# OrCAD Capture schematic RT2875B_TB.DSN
size A3
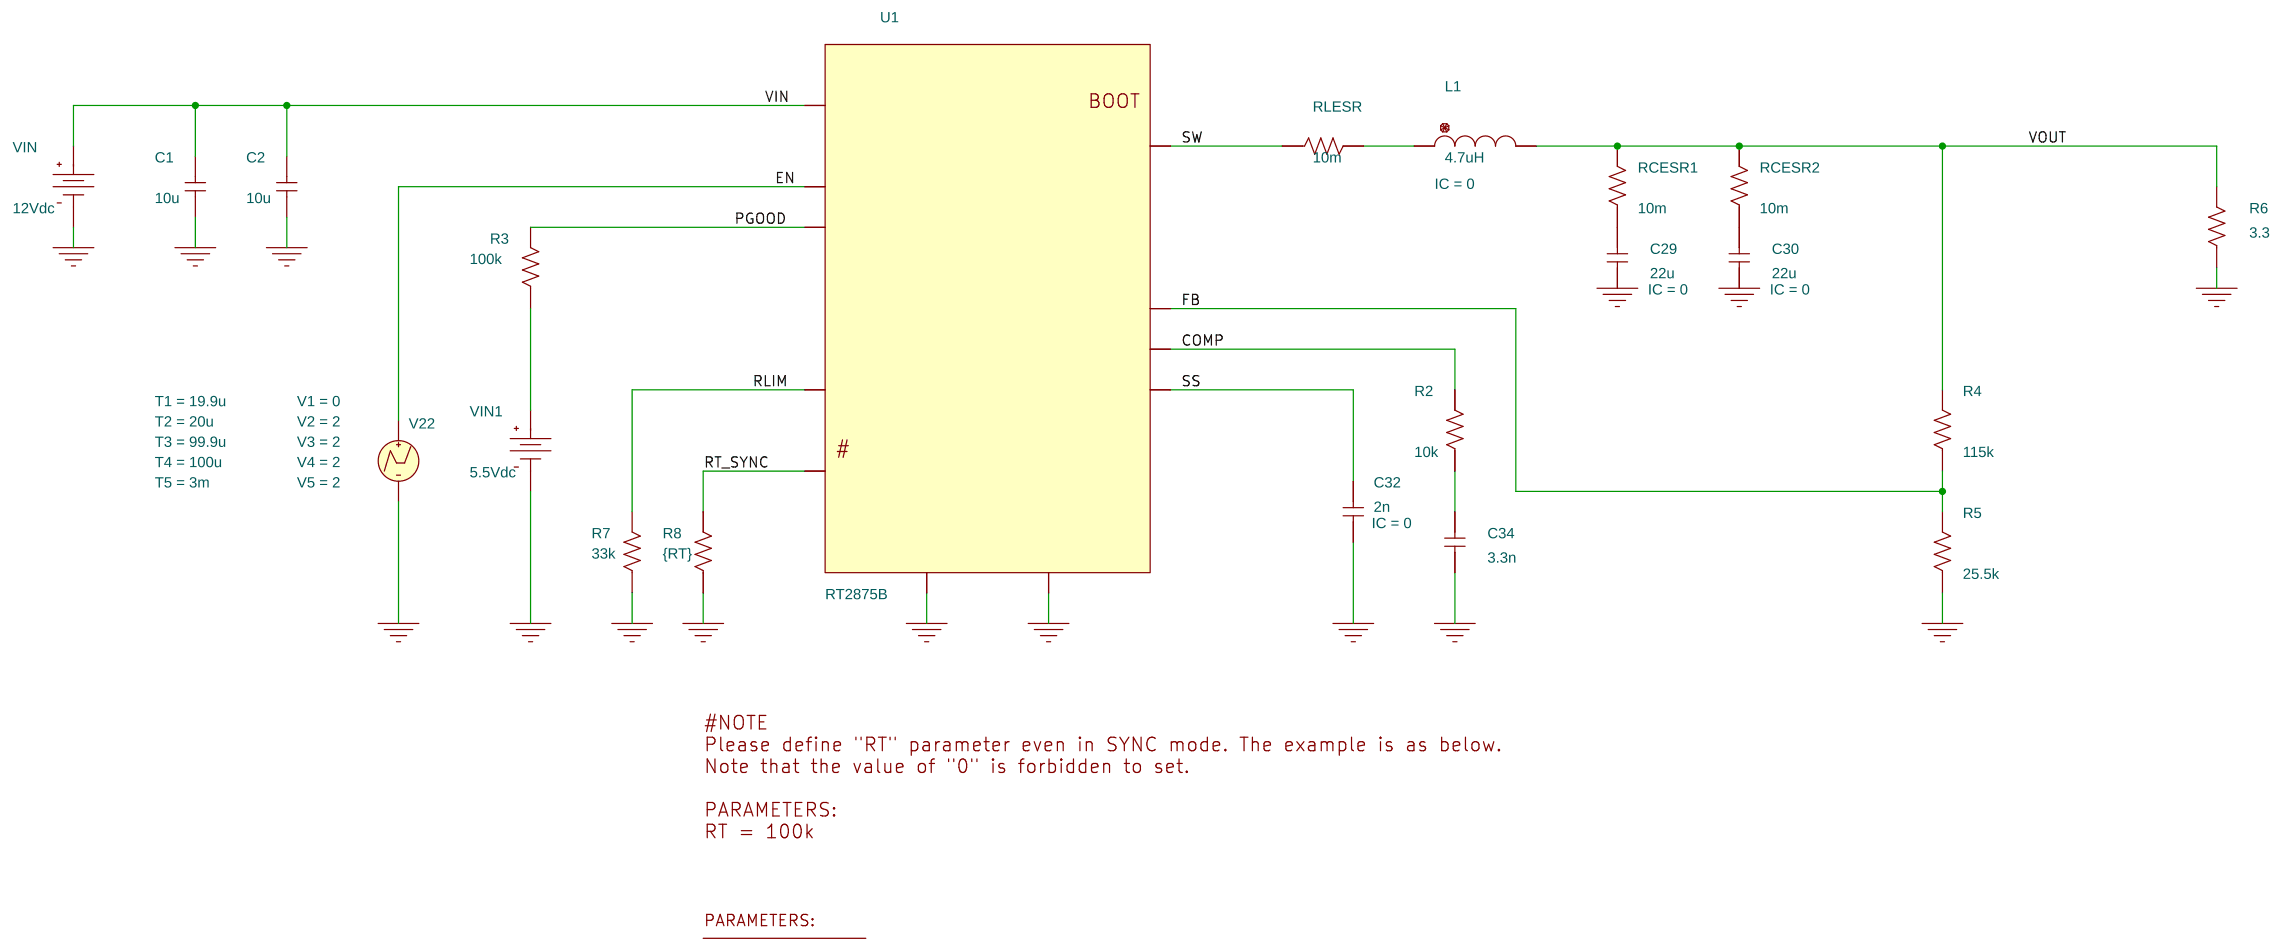
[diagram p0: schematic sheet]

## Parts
1  PARAM
C1  10u  [RAD/CK05]
C2  10u  [RAD/CK05]
C29  22u  [RAD/CK05]
C30  22u  [RAD/CK05]
C32  2n  [RAD/CK05]
C34  3.3n  [RAD/CK05]
L1  4.7uH  [DISC/.350x.175/LS.200x.100/.034]
R2  10k  [AX/RC05]
R3  100k  [AX/RC05]
R4  115k  [AX/RC05]
R5  25.5k  [AX/RC05]
R6  3.3  [AX/RC05]
R7  33k  [AX/RC05]
R8  {RT}  [AX/RC05]
RCESR1  10m  [AX/RC05]
RCESR2  10m  [AX/RC05]
RLESR  10m  [AX/RC05]
U1  RT2875B
V22  VPWL
VIN  VDC
VIN1  VDC

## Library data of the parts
1 = PARAM: RT: 100k
C1 C2 C34 = C
C29 C30 C32 = C: IC: 0
L1 = L: IC: 0
R2-R8 RCESR1 RCESR2 RLESR = R
U1 = RT2875B: PSpiceTemplate: X^@REFDES %AGND %COMP %EN %FB %PGND %PGOOD %RLIM %RT_SYNC %SS %SW %VIN @MODEL
V22 = VPWL: PSpiceTemplate: V^@REFDES %+ %- ?DC|DC @DC| ?AC|AC @AC|\n+PWL @T1 @V1 @T2 @V2 #T3/@T3 @V3/ #T4/@T4 @V4/ #T5/@T5 @V5/ #T6/@T6 @V6/ #T7/@T7 @V7/ #T8/@T8 @V8/ #T9/@T9 @V9/ #T10/@T10 @V10/; T1: 19.9u; T2: 20u; T3: 99.9u; T4: 100u; T5: 3m; V1: 0; V2: 2; V3: 2; V4: 2; V5: 2
VIN = VDC: DC: 12Vdc
VIN1 = VDC: DC: 5.5Vdc

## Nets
VIN: C1.2 C2.2 U1.VIN VIN.0(+)
0: C1.1 C2.1 C29.1 C30.1 C32.1 C34.1 R5.1 R6.1 R7.1 R8.1 U1.AGND U1.PGND V22.2(-) VIN.1(-) VIN1.1(-)
COMP: R2.2 U1.COMP
EN: U1.EN V22.1(+)
FB: R4.1 R5.2 U1.FB
PGOOD: R3.2 U1.PGOOD
RLIM: R7.2 U1.RLIM
RT_SYNC: R8.2 U1.RT_SYNC
SS: C32.2 U1.SS
SW: RLESR.1 U1.SW
VOUT: L1.2 R4.2 R6.2 RCESR1.2 RCESR2.2
N2668296: R3.1 VIN1.0(+)
N2673076: L1.1 RLESR.2
N2673110: C34.2 R2.1
N2673361: C29.2 RCESR1.1
N2673363: C30.2 RCESR2.1
